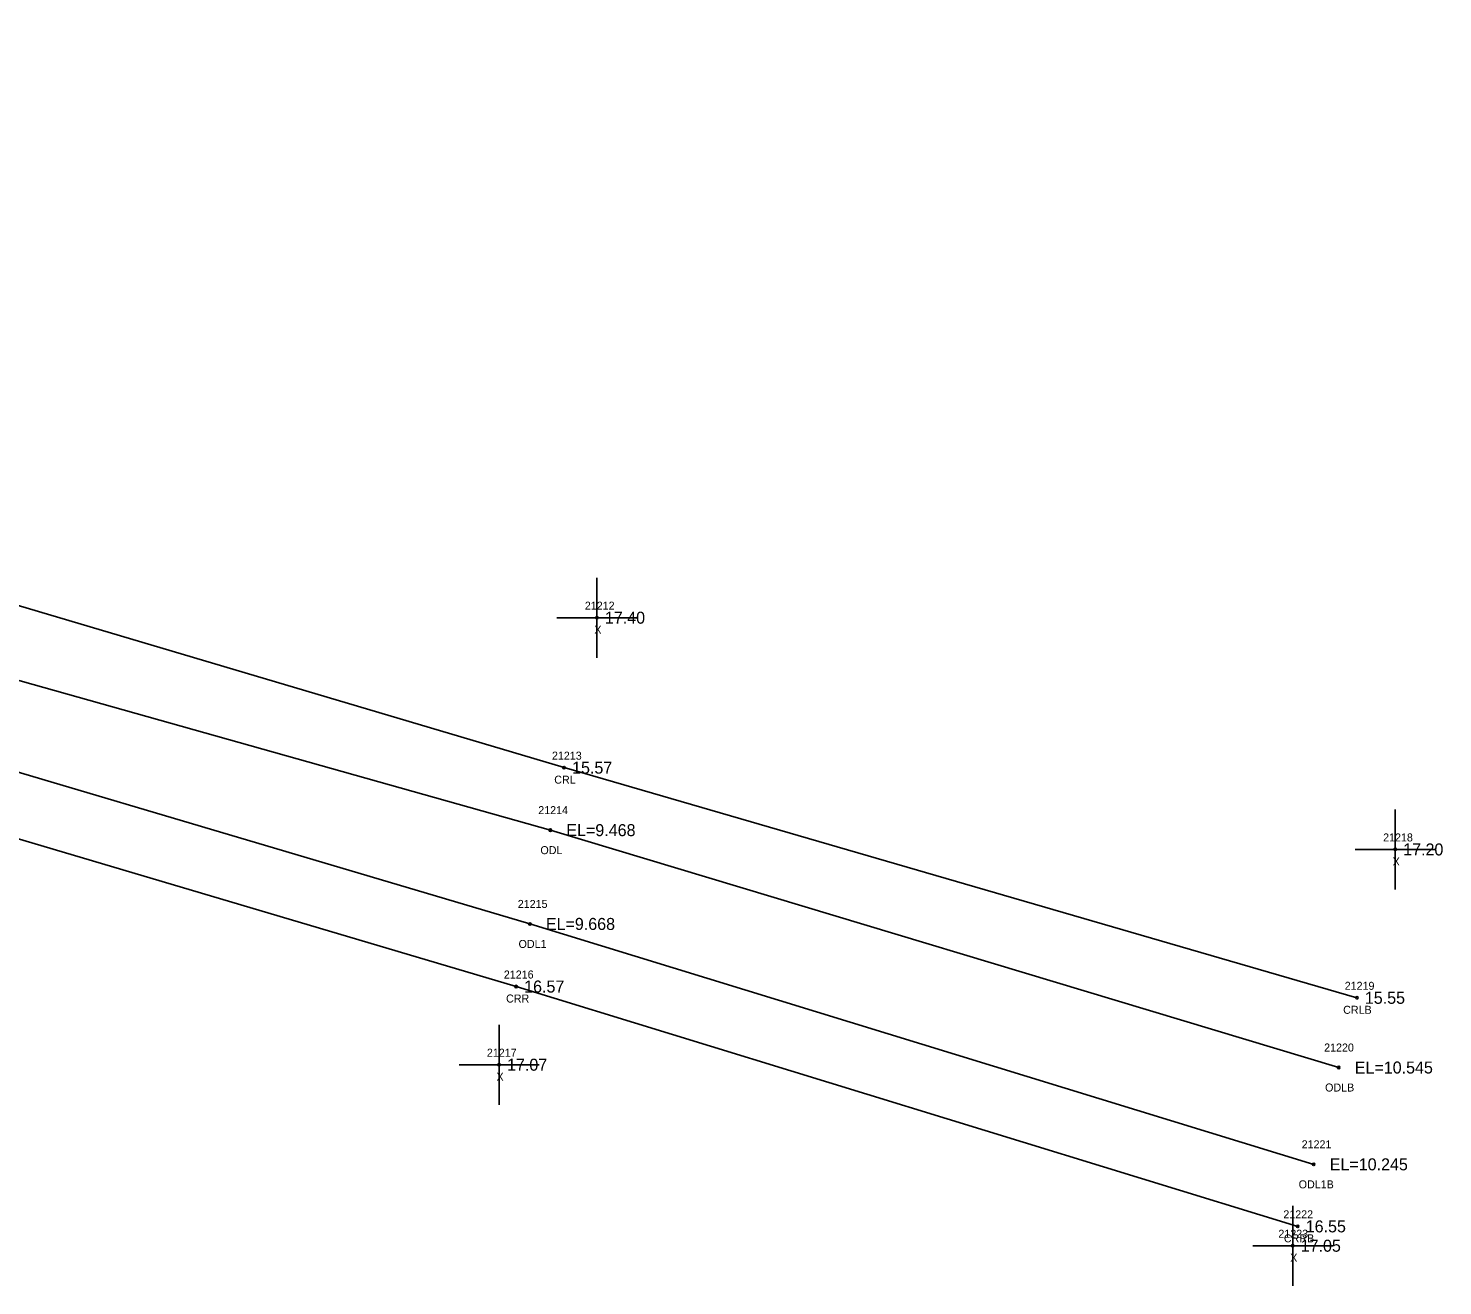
# Model space of a CAD drawing. Extents: x 2655177 to 2656219, y 761780 to 764748.
# Drawn here: x 2656042.3 to 2656219.1, y 763094.5 to 763251.6 of the extents above; entities that cross this region are included whole.
import ezdxf

# ---------------------------------------------------------------- set-up
doc = ezdxf.new("R2010")
doc.units = 0
for name, color, linetype in [('RD_EX_H2O', 7, 'Continuous'), ('RD_EX_H2O_txCode', 7, 'Continuous'), ('RD_EX_Misc', 7, 'Continuous'), ('RD_EX_Misc_txCode', 7, 'Continuous'), ('RD_EX_TX_H2O_ELEV', 7, 'Continuous'), ('RD_EX_TX_Misc_ELEV', 7, 'Continuous'), ('RD_SMD_Locator', 7, 'Continuous')]:
    doc.layers.add(name, color=color, linetype=linetype)

msp = doc.modelspace()

# ---------------------------------------------------------------- linework, layer by layer
at = {"layer": 'RD_EX_H2O'}
for points in [[(2655763.83, 763255.61), (2655817.49, 763238.63), (2655914.8, 763213.38), (2655950.66, 763206.21), (2656007.42, 763189.45), (2656109.25, 763159.23), (2656208.33, 763130.47)], [(2655756.39, 763249.8), (2655816.19, 763234.32), (2655913.6, 763207.5), (2656005.27, 763180.2), (2656107.53, 763151.42), (2656206.07, 763121.76)], [(2655730.43, 763238.59), (2655771.44, 763229.13), (2655791.17, 763220.85), (2655791.17, 763220.85), (2655810.24, 763214.7), (2655909.39, 763186.93), (2656001.09, 763162.18), (2656103.26, 763131.88), (2656200.94, 763101.91)], [(2655752.5, 763238.32), (2655812.56, 763222.36), (2655910.79, 763193.78), (2656002.9, 763169.97), (2656104.97, 763139.7), (2656202.94, 763109.66)]]:
    msp.add_lwpolyline(points, dxfattribs=at)
at = {"layer": 'RD_EX_Misc'}
for p, q in [((2656113.35, 763172.97), (2656113.35, 763182.97)), ((2656108.35, 763177.97), (2656118.35, 763177.97)), ((2656213.12, 763144.01), (2656213.12, 763154.01)), ((2656208.12, 763149.01), (2656218.12, 763149.01)), ((2656101.12, 763117.11), (2656101.12, 763127.11)), ((2656096.12, 763122.11), (2656106.12, 763122.11)), ((2656200.31, 763094.49), (2656200.31, 763104.49)), ((2656195.31, 763099.49), (2656205.31, 763099.49))]:
    msp.add_line(p, q, dxfattribs=at)
at = {"layer": 'RD_SMD_Locator'}
for centre in [(2656113.35, 763177.97), (2656109.25, 763159.23), (2656107.53, 763151.42), (2656213.12, 763149.01), (2656104.97, 763139.7), (2656103.26, 763131.88), (2656208.33, 763130.47), (2656101.12, 763122.11), (2656206.07, 763121.76), (2656202.94, 763109.66), (2656200.94, 763101.91), (2656200.31, 763099.49)]:
    msp.add_circle(centre, 0.15, dxfattribs=at)

# ---------------------------------------------------------------- texts
at = {"layer": 'RD_EX_H2O_txCode'}
for s, p in [('21213', (2656107.73, 763160.23)), ('CRL', (2656108.02, 763157.23)), ('21214', (2656106.02, 763153.42)), ('ODL', (2656106.29, 763148.42)), ('21215', (2656103.46, 763141.7)), ('ODL1', (2656103.56, 763136.7)), ('21216', (2656101.72, 763132.88)), ('21219', (2656206.81, 763131.47)), ('CRR', (2656102, 763129.88)), ('CRLB', (2656206.62, 763128.47)), ('21220', (2656204.24, 763123.76)), ('ODLB', (2656204.36, 763118.76)), ('21221', (2656201.43, 763111.66)), ('ODL1B', (2656201.06, 763106.66)), ('21222', (2656199.14, 763102.91)), ('CRRB', (2656199.21, 763099.91))]:
    msp.add_text(s, height=1, dxfattribs=at).set_placement(p)
at = {"layer": 'RD_EX_Misc_txCode'}
for s, p in [('21212', (2656111.84, 763178.97)), ('X', (2656113.03, 763175.97)), ('21218', (2656211.61, 763150.01)), ('X', (2656212.8, 763147.01)), ('21217', (2656099.6, 763123.11)), ('X', (2656100.8, 763120.11)), ('21223', (2656198.52, 763100.49)), ('X', (2656200, 763097.49))]:
    msp.add_text(s, height=1, dxfattribs=at).set_placement(p)
at = {"layer": 'RD_EX_TX_H2O_ELEV'}
for s, p in [('15.57', (2656110.25, 763158.48)), ('EL=9.468', (2656109.53, 763150.67)), ('EL=9.668', (2656106.97, 763138.95)), ('16.57', (2656104.26, 763131.13)), ('15.55', (2656209.33, 763129.72)), ('EL=10.545', (2656208.07, 763121.01)), ('EL=10.245', (2656204.94, 763108.91)), ('16.55', (2656201.94, 763101.16))]:
    msp.add_text(s, height=1.5, dxfattribs=at).set_placement(p)
at = {"layer": 'RD_EX_TX_Misc_ELEV'}
for s, p in [('17.40', (2656114.35, 763177.22)), ('17.20', (2656214.12, 763148.26)), ('17.07', (2656102.12, 763121.36)), ('17.05', (2656201.31, 763098.74))]:
    msp.add_text(s, height=1.5, dxfattribs=at).set_placement(p)

doc.saveas('drawing.dxf')
